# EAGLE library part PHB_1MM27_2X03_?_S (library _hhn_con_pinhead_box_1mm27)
Pin Header Box-Type, 1.27mm/0.5"/50mil Pitch, 2x03 Circuits, single gates in schematic Note: see library description for an important note about THT-version
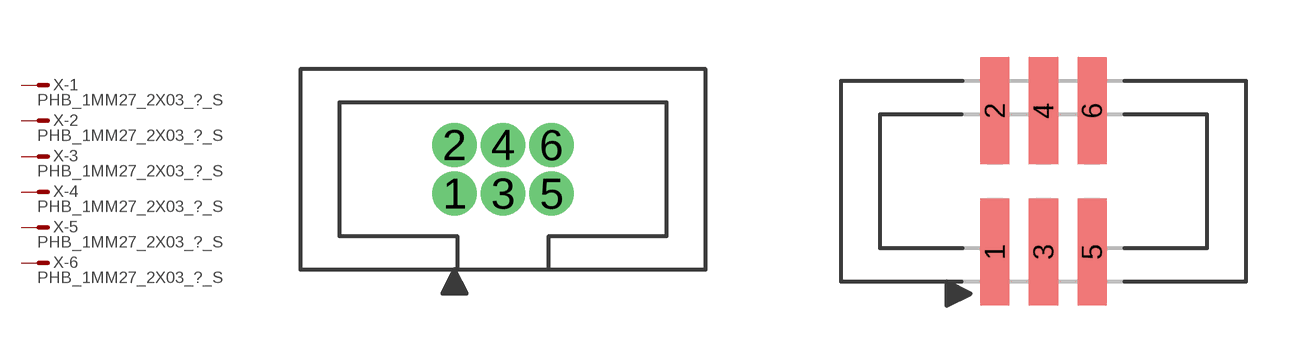
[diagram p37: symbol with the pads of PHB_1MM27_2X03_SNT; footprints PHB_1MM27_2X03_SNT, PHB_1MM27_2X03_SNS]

Designator prefix X; gates -1=M -2=M -3=M -4=M -5=M -6=M

## PHB_1MM27_2X03_SNT_S  [PHB_1MM27_2X03_SNT]
1  -1:S  pas
2  -2:S  pas
3  -3:S  pas
4  -4:S  pas
5  -5:S  pas
6  -6:S  pas

## PHB_1MM27_2X03_SNS_S  [PHB_1MM27_2X03_SNS]
Pads as for PHB_1MM27_2X03_SNT

## Footprint PHB_1MM27_2X03_SNT (pad centres in mm)
Pin Header Box-Type, 1.27mm Pitch, 2x03 circuits, Straight, No Locking, THT Important Note: Diameter in this lbr is set to a specific value (NOT 'auto' = 0), this is ignored by actual eagle versions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
drill 0.65 pad 1 round: 1 -1.27,-0.635; 2 -1.27,0.635; 3 0,-0.635; 4 0,0.635; 5 1.27,-0.635; 6 1.27,0.635

## Footprint PHB_1MM27_2X03_SNS (pad centres in mm)
Pin Header Box-Type, 1.27mm Pitch, 2x03 circuits, Straight, No Locking, SMT
smd 0.76 x 2.8: 1 -1.27,-1.85; 2 -1.27,1.85; 3 0,-1.85; 4 0,1.85; 5 1.27,-1.85; 6 1.27,1.85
